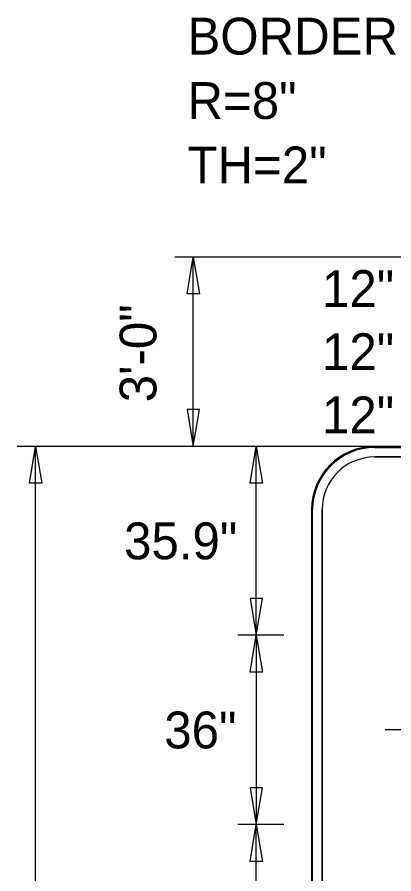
# Model space of a CAD drawing. Extents: x 2149961 to 2150220, y 145114 to 145240.
# Drawn here: x 2149978.76 to 2149984.73, y 145226.49 to 145240.06 of the extents above; entities that cross this region are included whole.
import ezdxf

# ---------------------------------------------------------------- set-up
doc = ezdxf.new("R2010")
doc.units = 0
for name, color, linetype in [('GSBWFILL', 7, 'Continuous'), ('GSCOLORFILL', 7, 'Continuous'), ('GSDIMS', 7, 'Continuous'), ('GSOUTLINE', 7, 'Continuous'), ('TEXT', 7, 'Continuous')]:
    doc.layers.add(name, color=color, linetype=linetype)

msp = doc.modelspace()

# ---------------------------------------------------------------- linework, layer by layer
at = {"layer": 'GSBWFILL'}
for p, q in [((2149997.93, 145233.262), (2149984.43, 145233.262)), ((2149984.43, 145233.095), (2149997.93, 145233.095)), ((2149983.43, 145232.262), (2149983.43, 145217.762)), ((2149983.596, 145217.762), (2149983.596, 145232.262))]:
    msp.add_line(p, q, dxfattribs=at)
for radius in [1, 0.833]:
    msp.add_arc((2149984.43, 145232.262), radius, 90, 180, dxfattribs=at)
at = {"layer": 'GSCOLORFILL'}
for p, q in [((2149997.93, 145233.262), (2149984.43, 145233.262)), ((2149997.93, 145233.262), (2149984.43, 145233.262)), ((2149997.93, 145233.262), (2149984.43, 145233.262)), ((2149984.43, 145233.245), (2149997.93, 145233.245)), ((2149984.43, 145233.095), (2149997.93, 145233.095)), ((2149983.43, 145232.262), (2149983.43, 145217.762)), ((2149983.43, 145232.262), (2149983.43, 145217.762)), ((2149983.43, 145232.262), (2149983.43, 145217.762)), ((2149983.446, 145217.762), (2149983.446, 145232.262)), ((2149983.596, 145217.762), (2149983.596, 145232.262))]:
    msp.add_line(p, q, dxfattribs=at)
for radius in [1, 1, 1, 0.983, 0.833]:
    msp.add_arc((2149984.43, 145232.262), radius, 90, 180, dxfattribs=at)
at = {"layer": 'GSDIMS'}
for p, q in [((2149981.992, 145236.263), (2149981.262, 145236.263)), ((2149981.554, 145233.262), (2149981.554, 145236.263)), ((2149985.492, 145236.263), (2149981.992, 145236.263)), ((2149979.492, 145233.262), (2149978.763, 145233.262)), ((2149979.054, 145216.762), (2149979.054, 145233.262)), ((2149982.992, 145233.262), (2149979.492, 145233.262)), ((2149981.992, 145233.262), (2149981.262, 145233.262)), ((2149985.492, 145233.262), (2149981.992, 145233.262)), ((2149982.992, 145233.262), (2149982.263, 145233.262)), ((2149982.554, 145230.27), (2149982.554, 145233.262)), ((2149982.992, 145230.27), (2149982.263, 145230.27)), ((2149982.992, 145230.27), (2149982.263, 145230.27)), ((2149982.554, 145230.27), (2149982.554, 145227.27)), ((2149982.992, 145227.27), (2149982.263, 145227.27)), ((2149982.992, 145227.27), (2149982.263, 145227.27)), ((2149982.554, 145219.295), (2149982.554, 145227.27))]:
    msp.add_line(p, q, dxfattribs=at)
for points in [[(2149981.554, 145236.263), (2149981.651, 145235.68), (2149981.457, 145235.68)], [(2149981.554, 145233.262), (2149981.651, 145233.845), (2149981.457, 145233.845)], [(2149979.054, 145233.262), (2149979.152, 145232.679), (2149978.957, 145232.679)], [(2149982.554, 145233.262), (2149982.652, 145232.679), (2149982.457, 145232.679)], [(2149982.554, 145230.27), (2149982.652, 145230.853), (2149982.457, 145230.853)], [(2149982.554, 145230.27), (2149982.652, 145229.687), (2149982.457, 145229.687)], [(2149982.554, 145227.27), (2149982.652, 145227.853), (2149982.457, 145227.853)], [(2149982.554, 145227.27), (2149982.652, 145226.687), (2149982.457, 145226.687)]]:
    msp.add_lwpolyline(points, close=True, dxfattribs=at)
at = {"layer": 'GSOUTLINE'}
for p, q in [((2149997.93, 145233.262), (2149984.43, 145233.262)), ((2149997.93, 145233.095), (2149984.43, 145233.095)), ((2149983.43, 145232.262), (2149983.43, 145217.762)), ((2149983.596, 145232.262), (2149983.596, 145217.762))]:
    msp.add_line(p, q, dxfattribs=at)
for radius in [1, 0.833]:
    msp.add_arc((2149984.43, 145232.262), radius, 90, 180, dxfattribs=at)
at = {"layer": 'TEXT'}
msp.add_line((2149991.18, 145228.77), (2149984.597, 145228.77), dxfattribs=at)

# ---------------------------------------------------------------- texts
at = {"layer": 'GSDIMS'}
for s, p in [('BORDER', (2149981.463, 145239.471)), ('R=8"', (2149981.463, 145238.45)), ('TH=2"', (2149981.463, 145237.43)), ('12"', (2149983.595, 145235.471)), ('12"', (2149983.595, 145234.471)), ('12"', (2149983.595, 145233.47)), ('35.9"', (2149980.458, 145231.474)), ('36"', (2149981.095, 145228.478))]:
    msp.add_text(s, height=0.5833, dxfattribs=at).set_placement(p)
msp.add_text('3\'-0"', height=0.5833, rotation=90, dxfattribs=at).set_placement((2149980.971, 145233.961))

doc.saveas('drawing.dxf')
